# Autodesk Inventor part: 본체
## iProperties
Company: 한국ATC센터
Created: 2014-08
Part Number: 본체
Document SubType Name: Modeling
Designer: KYOUNG IL JANG
Density: 2.71 g/cm^3
Material: 알루미늄-6061
Mass: 1881.43 g
Surface Area: 1142.15 cm^2
Volume: 694.253 cm^3
Author: KYOUNG IL JANG
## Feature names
1. M4 [Hole]
